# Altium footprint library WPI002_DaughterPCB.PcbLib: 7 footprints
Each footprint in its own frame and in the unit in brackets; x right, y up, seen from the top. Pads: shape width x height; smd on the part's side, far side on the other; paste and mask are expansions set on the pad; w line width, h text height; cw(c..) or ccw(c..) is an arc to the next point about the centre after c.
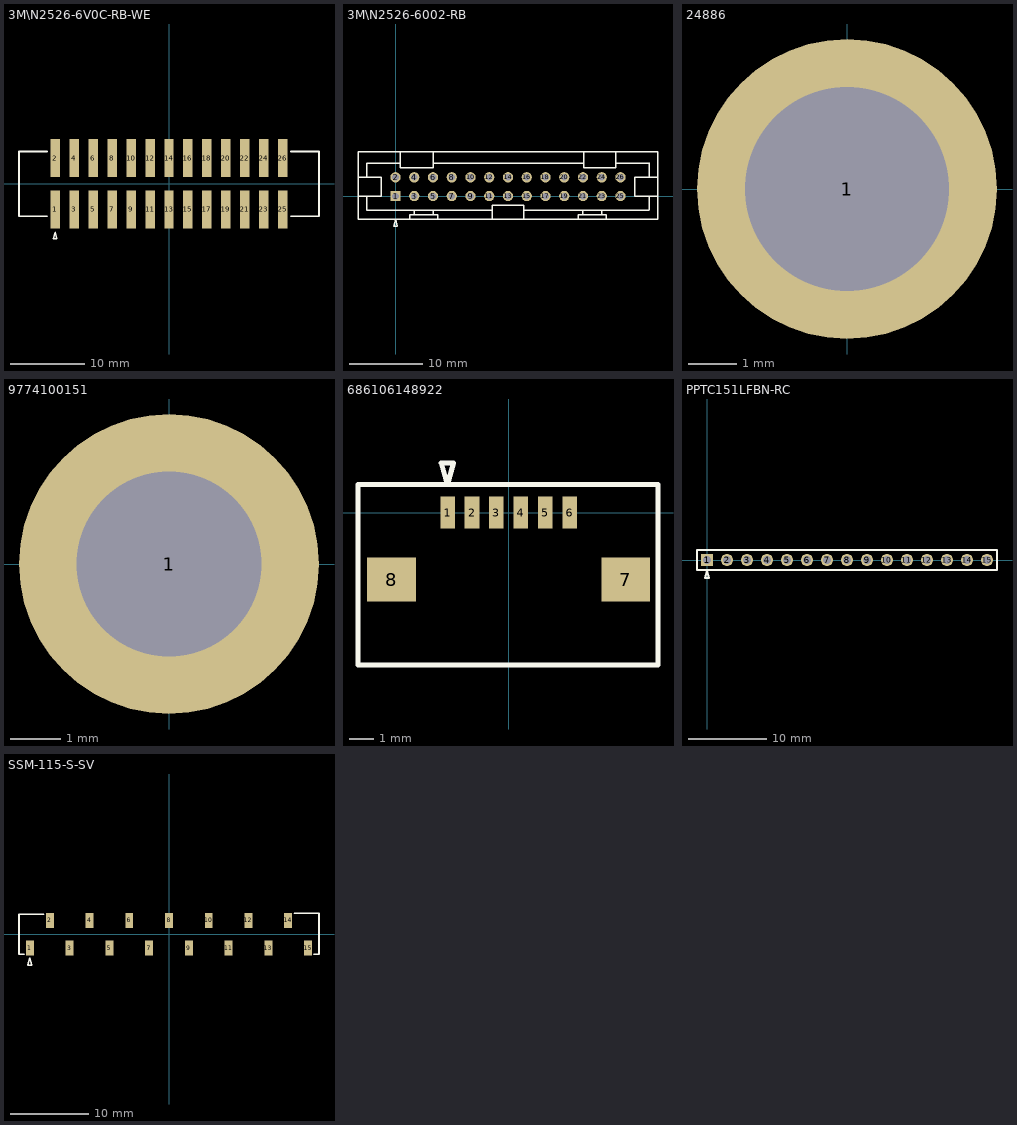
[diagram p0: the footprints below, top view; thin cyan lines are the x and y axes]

## 3M\N2526-6V0C-RB-WE [mil]
pads (26):
  rect 50x200 smd: 1(-600,-135) 2(-600,135) 3(-500,-135) 4(-500,135) 5(-400,-135) 6(-400,135) 7(-300,-135) 8(-300,135) 9(-200,-135) 10(-200,135) 11(-100,-135) 12(-100,135) 13(0,-135) 14(0,135) 15(100,-135) 16(100,135) 17(200,-135) 18(200,135) 19(300,-135) 20(300,135) 21(400,-135) 22(400,135) 23(500,-135) 24(500,135) 25(600,-135) 26(600,135)
Top Overlay:
  lines w8: -640,-170 -790,-170 -790,170 -640,170 ; 640,-170 790,-170 790,170 640,170 ; -610,-290 -590,-290 -600,-255 -610,-290
3D body "2526-6V0C-XX_step.stp": height 400, standoff 0, extent -794,-220 794,220

## 3M\N2526-6002-RB [mil]
pads (26):
  rect 55x55 hole 35: 1(0,0)
  round 55 hole 35: 2(0,100) 3(100,0) 4(100,100) 5(200,0) 6(200,100) 7(300,0) 8(300,100) 9(400,0) 10(400,100) 11(500,0) 12(500,100) 13(600,0) 14(600,100) 15(700,0) 16(700,100) 17(800,0) 18(800,100) 19(900,0) 20(900,100) 21(1000,0) 22(1000,100) 23(1100,0) 24(1100,100) 25(1200,0) 26(1200,100)
Top Overlay:
  lines w8: -200,0 -150,0 ; -200,100 -150,100 ; 25,235 25,150 ; 75,-125 75,-100 225,-100 225,-125 ; 100,-100 100,-75 ; 200,-100 200,-75 ; 200,235 200,150 ; 515,-125 515,-75 ; 685,-125 685,-75 ; 975,-125 975,-100 1125,-100 1125,-125 ; 1000,-100 1000,-75 ; 1005,150 1175,150 ; 1005,151 1005,235 ; 1005,175 200,175 200,150 ; 1100,-100 1100,-75 ; 1175,151 1175,235 ; 1175,175 1355,175 ; 1350,-75 685,-75 ; 1354,-75 1354,0 ; 1354,100 1354,175 ; 1400,0 1275,0 1275,100 1400,100 ; 25,150 200,150 ; 25,150 25,175 -154,175 -154,100 -75,100 -75,0 -154,0 -154,-75 515,-75 ; 25,150 200,150 ; 515,-75 515,-50 ; 515,-50 685,-50 ; 515,-50 685,-50 ; 685,-75 685,-50 ; -200,-125 -200,235 1400,235 1400,-125 -200,-125 ; -10,-160 10,-160 0,-125 -10,-160
3D body "2526-6002-XX_step.stp": height 370, standoff -132, extent -194,-112 1394,228

## 24886 [mil]
pads (1):
  round 244 hole 166: 1(0,0)
3D body "keystone-PN24886.STEP": height 393.7, standoff -60, extent -109.49,-109.5 109.51,109.5

## 9774100151 [mm]
pads (1):
  round 6 hole 3.7: 1(0,0)
3D body "9774100151_Download_STP_9774100151_rev1.stp": height 10, standoff -1.4, extent -2.55,-2.55 2.55,2.55

## 686106148922 [mm]
pads (8):
  rect 0.6x1.3 smd: 1(-2.5,0) 2(-1.5,0) 3(-0.5,0) 4(0.5,0) 5(1.5,0) 6(2.5,0)
  rect 2x1.8 smd: 7(4.8,-2.75) 8(-4.8,-2.75)
Top Overlay:
  lines w0.203: -6.175,-6.25 -6.175,1.143 6.125,1.143 6.125,-6.25 -6.175,-6.25 ; -2.764,2.032 -2.256,2.032 -2.51,1.143 -2.764,2.032
3D body "686106148922_Download_STP_686106148922_rev1.stp": height 2.2, standoff -0.05, extent -5.3,-6.25 5.3,0.25

## PPTC151LFBN-RC [mil]
pads (15):
  rect 60x60 hole 40: 1(0,0)
  round 60 hole 40: 2(100,0) 3(200,0) 4(300,0) 5(400,0) 6(500,0) 7(600,0) 8(700,0) 9(800,0) 10(900,0) 11(1000,0) 12(1100,0) 13(1200,0) 14(1300,0) 15(1400,0)
Top Overlay:
  lines w8: -50,-50 -50,50 1450,50 1450,-50 -50,-50 ; -10,-90 10,-90 0,-55 -10,-90
3D body "Conn_Sullins_PPTC151LFBN-RC_eec.STEP": height 334.65, standoff -125.98, extent -59.84,-49.99 1459.85,50.01

## SSM-115-S-SV [mil]
pads (15):
  rect 40x75 smd: 1(-700,-70) 2(-600,70) 3(-500,-70) 4(-400,70) 5(-300,-70) 6(-200,70) 7(-100,-70) 8(0,70) 9(100,-70) 10(200,70) 11(300,-70) 12(400,70) 13(500,-70) 14(600,70) 15(700,-70)
Top Overlay:
  lines w8: -730,-100 -755,-100 -755,100 -630,100 ; 630,105 755,105 755,-100 730,-100 ; -710,-155 -690,-155 -700,-120 -710,-155
3D body "SSM-115-S-SV.stp": height 295, standoff 0, extent -750,-89.99 750,90.01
